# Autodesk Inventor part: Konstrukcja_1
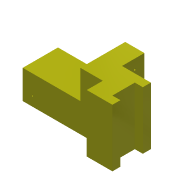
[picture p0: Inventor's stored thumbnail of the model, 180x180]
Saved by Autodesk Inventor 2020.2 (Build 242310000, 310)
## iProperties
Created: 2014-07
Part Number: Konstrukcja_1
Material: Ogólny
Document SubType Name: Modeling
Designer: F.Stasiak
Density: 1 g/cm^3
Appearance: Żółta
Catalog Web Link: www.expertbooks.pl
Manager: www.cadconsulting.pl
Company: Fabian Stasiak CAD Consulting
Author: F.Stasiak
Subject: Zbiór ćwiczeń. Autodesk Inventor 2020. Kurs Professional
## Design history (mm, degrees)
sketch "Szkic1"
  geometry: L1 (0, 0)-(2500, 0); L2 (2500, 0)-(2500, -500); L3 (2500, -500)-(3300, -500); L4 (3300, -500)-(3300, 700); L5 (3300, 700)-(2400, 700); L6 (2400, 700)-(2400, 1400); L7 (2400, 1400)-(1300, 1400); L8 (1300, 1400)-(1300, 1100); L9 (1300, 1100)-(0, 1100); L10 (0, 1100)-(0, 0)
  constraints: 20 end point, 9 perpendicular, 1 horizontal
  dimensions: "d0" = 2500 distance of L1.start L1.end; "d1" = 500 distance of L1.end L2.end; "d2" = 800 distance of L2.end L3.end; "d3" = 1200 distance of L3.end L4.end; "d4" = 900 distance of L4.end L5.end; "d5" = 700 distance of L5.end L6.end; "d6" = 1100 distance of L6.end L7.end; "d7" = 300 distance of L7.end L8.end
extrude "Wyciągnięcie proste1" new body sketch "Szkic1" distance "d8" = 1800; taper "d9" = 0 deg
sketch "Szkic3"
  geometry: L1 (0, 0)-(2500, 0) reference; L2 (0, 0)-(0, 1800) reference; 1 further point
  dimensions: "d14" = 300 distance from line of point (300, 300) L1; "d15" = 300 distance from line of L2 point (300, 300)
hole "Otwór1" sketch "Szkic3" at (300, 300) diameter "d16" = 50; stored, may be unused: countersink angle "d20" = 90 deg, drill point angle "d22" = 118 deg; dims "d17" = 6, "d18" = 4, "d19" = 2, "d21" = 100
sketch "Szkic7"
  geometry: L1 (3300, -500)-(3300, 700) reference; L2 (3300, 450)-(3050, 450); L3 (3050, 450)-(3050, -250); L4 (3050, -250)-(3300, -250); L5 (2500, -500)-(3300, -500) reference; L6 (3300, 700)-(2400, 700) reference; 1 further point
  constraints: 6 end point, 2 perpendicular, 2 point on line, 1 horizontal
  dimensions: "d59" = 250 distance between parallel lines of L5 L4; "d60" = 250 distance between parallel lines of L6 L2 (= d59); "d61" = 250 distance of L3.end L4.end (= d59)
extrude "Wyciągnięcie proste4" cut sketch "Szkic7" extent not by distance; stored distance "d62" = 10; taper "d63" = 0 deg
sketch "Szkic9"
  geometry: L1 (1200, 650)-(-600, 650) reference; L2 (-600, -50)-(-600, 650) reference; 1 further point
  dimensions: "d89" = 300 distance from line of L1 point (-300, 350); "d90" = 300 distance from line of L2 point (-300, 350)
hole "Otwór5" sketch "Szkic9" at (-300, 350) diameter "d80" = 50; stored, may be unused: drill point angle "d75" = 118 deg, countersink angle "d76" = 90 deg; dims "d72" = 6, "d77" = 2, "d78" = 4, "d79" = 100
sketch "Szkic11"
  geometry: L1 (0, 0)-(0, 1800) reference; L2 (0, 1800)-(2500, 1800) reference; L3 (0, 900)-(1800, 900); L4 (1800, 900)-(1800, 1800)
  constraints: 4 end point, 1 horizontal, 1 midpoint, 1 perpendicular, 1 point on line
  dimensions: "d92" = 1800 distance of L3.start L3.end
extrude "Wyciągnięcie proste6" cut sketch "Szkic11" extent not by distance; stored distance "d93" = 10; taper "d94" = 0 deg
node "Bryła1"
feature "耀䁑"
